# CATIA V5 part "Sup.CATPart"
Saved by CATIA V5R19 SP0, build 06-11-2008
Part number: Sup
Publications: "L_i", "H", "e", "La"
Bounding box of the stored display mesh (mm): x -10 to 100, y 0 to 40, z 0 to 90
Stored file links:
  G:\EU_thinkMotion\CFAO_2010\MMS_groupe3\MMS_groupe3\A reprendre\evulliez\evulliez\Sup.CATPart
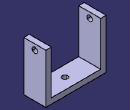
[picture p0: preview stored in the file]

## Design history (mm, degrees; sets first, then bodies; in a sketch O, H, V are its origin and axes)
Parameters
  L_i = 90 mm
  H = 90 mm
  e = 10 mm
  La = 40 mm
Body1 (main body)
  Sketch1 on yz-plane, origin (0, 0, 0), H (0, 1, 0), V (0, 0, 1)
    line L1 (0, 0) -> (40, 0)
    line L2 (40, 0) -> (40, 90)
    line L3 (40, 90) -> (0, 90)
    line L4 (0, 90) -> (0, 0)
    length L3 = 40 {= La}
    length L2 = 90 {= H}
    horizontal: L1 H, L3 H
    vertical: L2 V, L4 V
  Pad1: profile Sketch1, direction (-1, 0, 0), length 10 {= e}
  Sketch2 on start face of Pad1, origin (0, 0, 0), H (0, 1, 0), V (0, 0, 1)
    line L1 (0, 0) -> (40, 0)
    line L2 (40, 0) -> (40, 10)
    line L3 (40, 10) -> (0, 10)
    line L4 (0, 10) -> (0, 0)
    length L2 = 10 {= e}
    length L1 = 40 {= La}
    horizontal: L1 H, L3 H
    vertical: L2 V, L4 V
  Pad2: profile Sketch2, direction (1, 0, 0), length 45 {= L_i /2}
  Mirror1: of Pad1, Pad2, about end face of Pad2
  Point1: type OnPlane, Support end face of Pad1, H -20 {= -La /2}, V 80 {= H -10mm}, Direction (0, -1, 0)
  Sketch3 on end face of Pad1, origin (-10, 20, 90), H (0, 1, 0), V (0, 0, -1)
    point P1 (0, 10)
    reference projected point E1 (0, 10) from Point1
    coincidence: E1 P1
  Hole1: placed by Sketch3, at (-10, 20, 80) direction (1, 0, 0), diameter 10, through (limit type 3)
  Point2: type OnPlane, Support face of Mirror1, H 45 {= L_i /2}, V -20 {= -La /2}, Direction (1, 0, 0)
  Sketch4 on face of Mirror1, origin (0, 20, 0), H (1, 0, 0), V (0, -1, 0)
    point P1 (45, 0)
    reference projected point E1 (45, 0) from Point2
    coincidence: E1 P1
  Hole2: placed by Sketch4, at (45, 20, 0) direction (0, 0, 1), diameter 10, through (limit type 3)
Relations
  Pad1.FirstLimit.Length = e e (deactivated)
